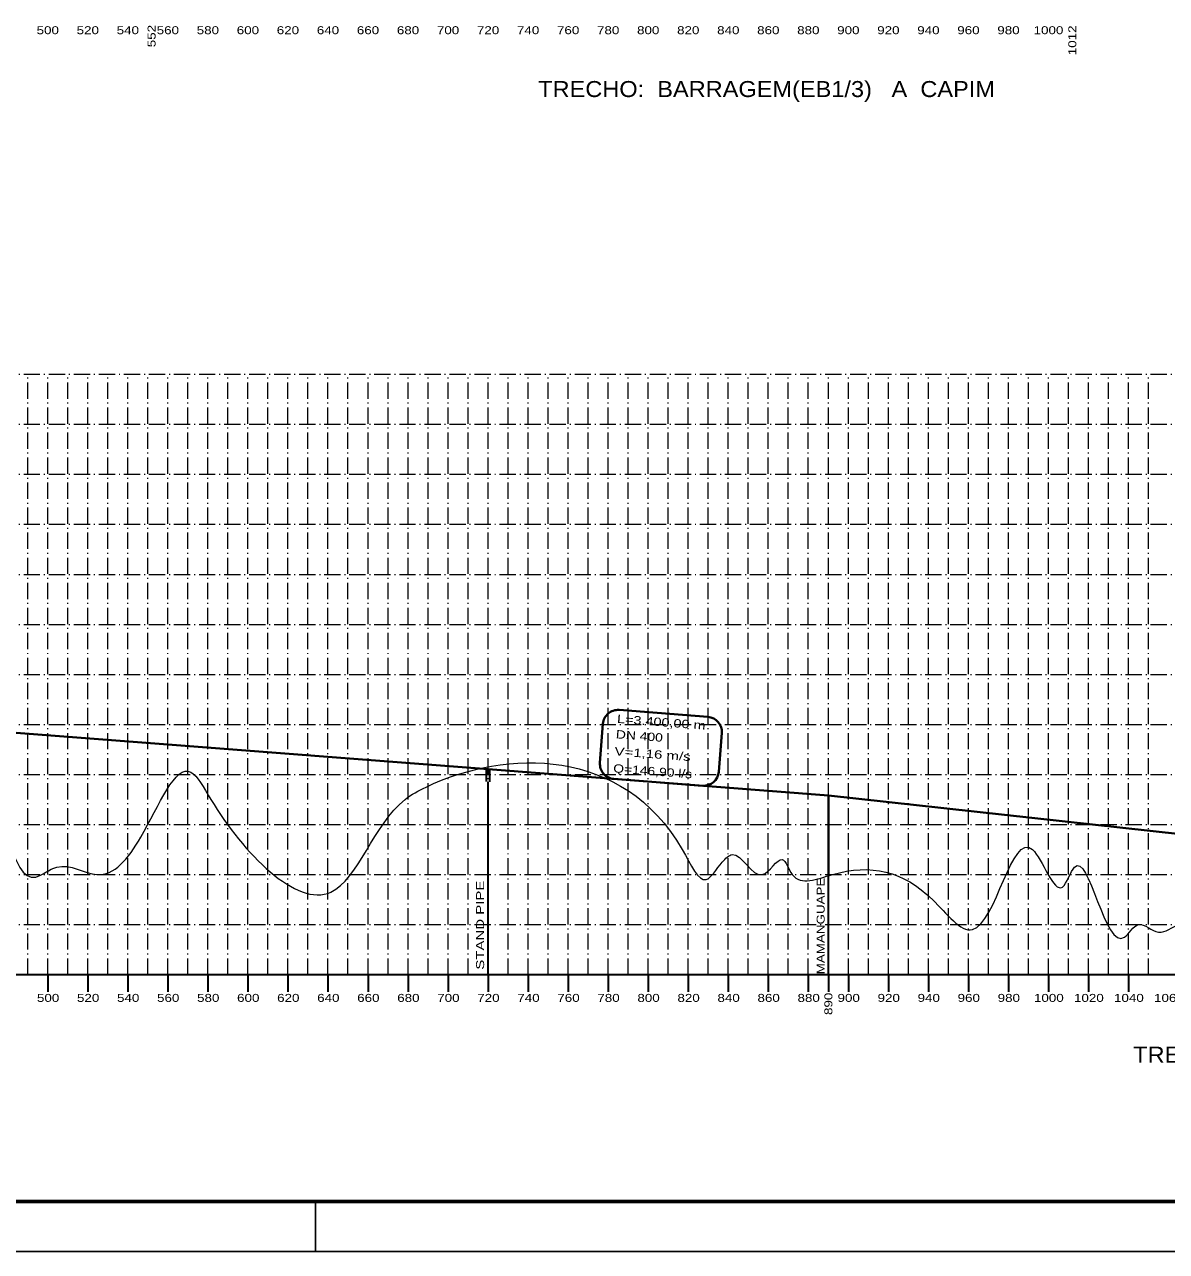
# Model space of a CAD drawing. Extents: x 0 to 1682, y 0 to 1188.
# Drawn here: x 495.5 to 951.9, y -0.1 to 490.3 of the extents above; entities that cross this region are included whole.
import ezdxf
from ezdxf.enums import TextEntityAlignment as Align

# ---------------------------------------------------------------- set-up
doc = ezdxf.new("R2010")
doc.units = 0
doc.header["$LTSCALE"] = 1.3
doc.linetypes.add('DOT_DASHED', pattern=[7.7, 5, -1.2, 0.3, -1.2])
for name, color, linetype, lineweight in [('1', 7, 'DOT_DASHED', 13), ('56', 7, 'Continuous', 13), ('62', 7, 'Continuous', 13), ('63', 7, 'Continuous', 25), ('7', 7, 'Continuous', 35), ('9', 7, 'Continuous', 40)]:
    doc.layers.add(name, color=color, linetype=linetype, lineweight=lineweight)
doc.layers.add('24', color=7, linetype='Continuous')

msp = doc.modelspace()

# ---------------------------------------------------------------- linework, layer by layer
at = {"layer": '1'}
for p, q in [((104.775, 350.521), (1145.575, 350.521)), ((496.775, 110.521), (496.775, 350.521)), ((504.775, 110.521), (504.775, 350.521)), ((512.775, 110.521), (512.775, 350.521)), ((520.775, 110.521), (520.775, 350.521)), ((528.775, 110.521), (528.775, 350.521)), ((536.775, 110.521), (536.775, 350.521)), ((544.775, 110.521), (544.775, 350.521)), ((552.775, 110.521), (552.775, 350.521)), ((560.775, 110.521), (560.775, 350.521)), ((568.775, 110.521), (568.775, 350.521)), ((576.775, 110.521), (576.775, 350.521)), ((584.775, 110.521), (584.775, 350.521)), ((592.775, 110.521), (592.775, 350.521)), ((600.775, 110.521), (600.775, 350.521)), ((608.775, 110.521), (608.775, 350.521)), ((616.775, 110.521), (616.775, 350.521)), ((624.775, 110.521), (624.775, 350.521)), ((632.775, 110.521), (632.775, 350.521)), ((640.775, 110.521), (640.775, 350.521)), ((648.775, 110.521), (648.775, 350.521)), ((656.775, 110.521), (656.775, 350.521)), ((664.775, 110.521), (664.775, 350.521)), ((672.775, 110.521), (672.775, 350.521)), ((680.775, 110.521), (680.775, 350.521)), ((688.775, 110.521), (688.775, 350.521)), ((696.775, 110.521), (696.775, 350.521)), ((704.775, 110.521), (704.775, 350.521)), ((712.775, 110.521), (712.775, 350.521)), ((720.775, 110.521), (720.775, 350.521)), ((728.775, 110.521), (728.775, 350.521)), ((736.775, 110.521), (736.775, 350.521)), ((744.775, 110.521), (744.775, 350.521)), ((752.775, 110.521), (752.775, 350.521)), ((760.775, 110.521), (760.775, 350.521)), ((768.775, 110.521), (768.775, 350.521)), ((776.775, 110.521), (776.775, 350.521)), ((784.775, 110.521), (784.775, 350.521)), ((792.775, 110.521), (792.775, 350.521)), ((800.775, 110.521), (800.775, 350.521)), ((808.775, 110.521), (808.775, 350.521)), ((816.775, 110.521), (816.775, 350.521)), ((824.775, 110.521), (824.775, 350.521)), ((832.775, 110.521), (832.775, 350.521)), ((840.775, 110.521), (840.775, 350.521)), ((848.775, 110.521), (848.775, 350.521)), ((856.775, 110.521), (856.775, 350.521)), ((864.775, 110.521), (864.775, 350.521)), ((872.775, 110.521), (872.775, 350.521)), ((880.775, 110.521), (880.775, 350.521)), ((888.775, 110.521), (888.775, 350.521)), ((896.775, 110.521), (896.775, 350.521)), ((904.775, 110.521), (904.775, 350.521)), ((912.775, 110.521), (912.775, 350.521)), ((920.775, 110.521), (920.775, 350.521)), ((928.775, 110.521), (928.775, 350.521)), ((936.775, 110.521), (936.775, 350.521)), ((944.775, 110.521), (944.775, 350.521)), ((104.775, 330.521), (1145.575, 330.521)), ((104.775, 310.521), (1145.575, 310.521)), ((104.775, 290.521), (1145.575, 290.521)), ((104.775, 270.521), (1145.575, 270.521)), ((104.775, 250.521), (1145.575, 250.521)), ((104.775, 230.521), (1145.575, 230.521)), ((104.775, 210.521), (1145.575, 210.521)), ((104.775, 190.521), (1145.575, 190.521)), ((104.775, 170.521), (1145.575, 170.521)), ((104.775, 150.521), (1145.575, 150.521)), ((104.775, 130.521), (1145.575, 130.521))]:
    msp.add_line(p, q, dxfattribs=at)
at = {"layer": '56'}
msp.add_spline([(104.775, 155.521), (114.375, 150.521), (116.375, 145.521), (117.875, 149.271), (119.975, 160.521), (121.575, 150.521), (123.175, 160.521), (127.975, 170.521), (132.775, 183.521), (136.775, 170.521), (139.175, 155.521), (149.575, 188.521), (177.575, 175.521), (202.375, 180.521), (205.575, 178.521), (209.575, 180.521), (213.575, 183.521), (221.575, 176.521), (229.575, 179.521), (241.575, 175.521), (257.575, 180.521), (273.575, 168.521), (286.375, 190.521), (290.375, 195.521), (303.175, 178.521), (318.375, 190.521), (328.775, 187.521), (340.775, 190.521), (348.775, 180.521), (358.375, 193.521), (366.375, 184.521), (376.775, 200.521), (397.575, 190.521), (415.975, 202.521), (446.375, 175.521), (458.375, 185.521), (463.175, 180.521), (475.975, 181.521), (499.975, 149.521), (508.375, 153.521), (524.375, 150.521), (541.975, 165.521), (561.975, 191.521), (569.975, 180.521), (617.975, 143.521), (647.575, 180.521), (655.975, 185.521), (758.375, 160.521), (767.975, 148.521), (774.375, 155.521), (778.375, 158.521), (790.375, 150.521), (798.375, 156.521), (802.375, 150.521), (818.375, 150.521), (858.375, 140.521), (874.375, 128.521), (898.375, 160.521), (910.375, 145.521), (915.175, 153.521), (935.175, 125.521), (940.775, 130.521), (948.775, 127.521), (956.775, 130.521), (975.975, 120.521), (984.775, 118.521), (995.175, 125.521), (1023.975, 118.521), (1029.575, 120.521), (1033.575, 118.521), (1040.775, 123.521), (1048.775, 118.521), (1068.775, 125.521), (1084.775, 118.521), (1091.175, 123.521), (1095.175, 120.521), (1099.975, 122.521), (1107.975, 117.521), (1114.375, 120.521), (1130.375, 118.521), (1145.575, 118.521)], degree=3, dxfattribs=at)
at = {"layer": '62', "lineweight": 35}
for p, q in [((680.775, 110.521), (680.775, 187.657)), ((816.775, 110.521), (816.775, 150.725)), ((104.775, 110.521), (1145.575, 110.521)), ((504.775, 110.521), (504.775, 103.693)), ((520.775, 110.521), (520.775, 103.693)), ((536.775, 110.521), (536.775, 103.693)), ((552.775, 110.521), (552.775, 103.693)), ((568.775, 110.521), (568.775, 103.693)), ((584.775, 110.521), (584.775, 103.693)), ((600.775, 110.521), (600.775, 103.693)), ((616.775, 110.521), (616.775, 103.693)), ((632.775, 110.521), (632.775, 103.693)), ((648.775, 110.521), (648.775, 103.693)), ((664.775, 110.521), (664.775, 103.693)), ((680.775, 110.521), (680.775, 103.693)), ((696.775, 110.521), (696.775, 103.693)), ((712.775, 110.521), (712.775, 103.693)), ((728.775, 110.521), (728.775, 103.693)), ((744.775, 110.521), (744.775, 103.693)), ((760.775, 110.521), (760.775, 103.693)), ((776.775, 110.521), (776.775, 103.693)), ((792.775, 110.521), (792.775, 103.693)), ((808.775, 110.521), (808.775, 103.693)), ((816.775, 110.521), (816.775, 103.693)), ((824.775, 110.521), (824.775, 103.693)), ((840.775, 110.521), (840.775, 103.693)), ((856.775, 110.521), (856.775, 103.693)), ((872.775, 110.521), (872.775, 103.693)), ((888.775, 110.521), (888.775, 103.693)), ((904.775, 110.521), (904.775, 103.693)), ((920.775, 110.521), (920.775, 103.693)), ((936.775, 110.521), (936.775, 103.693))]:
    msp.add_line(p, q, dxfattribs=at)
at = {"layer": '63', "lineweight": 60}
msp.add_line((1661.832, 19.881), (49.832, 19.881), dxfattribs=at)
at = {"layer": '63'}
msp.add_line((611.832, -0.119), (611.832, 19.881), dxfattribs=at)
for points in [[(-0.168, -0.119), (1681.832, -0.119), (1681.832, 1187.881)], [(-0.168, -0.119), (1681.832, -0.119), (-0.168, -0.119)]]:
    msp.add_lwpolyline(points, dxfattribs=at)
at = {"layer": '63', "lineweight": 60}
msp.add_lwpolyline([(951.544, 19.881), (49.832, 19.881), (49.832, 1167.881)], dxfattribs=at)
at = {"layer": '7'}
msp.add_line((680.081, 187.706), (680.081, 192.439), dxfattribs=at)
msp.add_lwpolyline([(681.468, 187.603), (681.468, 192.439), (680.081, 192.439)], dxfattribs=at)
at = {"layer": '9'}
for p, q in [((733.134, 216.31), (768.663, 213.569)), ((726.69, 210.789), (725.49, 195.225)), ((774.183, 207.126), (772.983, 191.562)), ((731.011, 188.782), (766.539, 186.041)), ((816.775, 150.725), (816.775, 182.165))]:
    msp.add_line(p, q, dxfattribs=at)
msp.add_lwpolyline([(104.775, 243.105), (148.775, 235.835), (256.775, 225.365), (680.775, 192.657), (816.775, 182.165), (1145.575, 145.975)], dxfattribs=at)
for centre, start, end in [((732.673, 210.328), 85.58878, 175.58878), ((768.201, 207.587), 355.58878, 85.58878), ((731.472, 194.764), 175.58877, 265.58877), ((767, 192.023), 265.58877, 355.58877)]:
    msp.add_arc(centre, 6, start, end, dxfattribs=at)

# ---------------------------------------------------------------- texts
at = {"layer": '24'}
for s, height, width, p in [('500', 3.2, 1.25, (504.775, 486.422)), ('520', 3.2, 1.25, (520.775, 486.422)), ('540', 3.2, 1.25, (536.775, 486.422)), ('560', 3.2, 1.25, (552.775, 486.422)), ('580', 3.2, 1.25, (568.775, 486.422)), ('600', 3.2, 1.25, (584.775, 486.422)), ('620', 3.2, 1.25, (600.775, 486.422)), ('640', 3.2, 1.25, (616.775, 486.422)), ('660', 3.2, 1.25, (632.775, 486.422)), ('680', 3.2, 1.25, (648.775, 486.422)), ('700', 3.2, 1.25, (664.775, 486.422)), ('720', 3.2, 1.25, (680.775, 486.422)), ('740', 3.2, 1.25, (696.775, 486.422)), ('760', 3.2, 1.25, (712.775, 486.422)), ('780', 3.2, 1.25, (728.775, 486.422)), ('800', 3.2, 1.25, (744.775, 486.422)), ('820', 3.2, 1.25, (760.775, 486.422)), ('840', 3.2, 1.25, (776.775, 486.422)), ('860', 3.2, 1.25, (792.775, 486.422)), ('880', 3.2, 1.25, (808.775, 486.422)), ('900', 3.2, 1.25, (824.775, 486.422)), ('920', 3.2, 1.25, (840.775, 486.422)), ('940', 3.2, 1.25, (856.775, 486.422)), ('960', 3.2, 1.25, (872.775, 486.422)), ('980', 3.2, 1.25, (888.775, 486.422)), ('1000', 3.2, 1.25, (904.775, 486.422)), ('TRECHO:  BARRAGEM(EB1/3)   A  CAPIM', 6.4, 1.1, (792.086, 461.309)), ('500', 3.2, 1.25, (504.915, 99.629)), ('520', 3.2, 1.25, (520.915, 99.629)), ('540', 3.2, 1.25, (536.915, 99.629)), ('560', 3.2, 1.25, (552.915, 99.629)), ('580', 3.2, 1.25, (568.915, 99.629)), ('600', 3.2, 1.25, (584.915, 99.629)), ('620', 3.2, 1.25, (600.915, 99.629)), ('640', 3.2, 1.25, (616.915, 99.629)), ('660', 3.2, 1.25, (632.915, 99.629)), ('680', 3.2, 1.25, (648.915, 99.629)), ('700', 3.2, 1.25, (664.915, 99.629)), ('720', 3.2, 1.25, (680.915, 99.629)), ('740', 3.2, 1.25, (696.915, 99.629)), ('760', 3.2, 1.25, (712.915, 99.629)), ('780', 3.2, 1.25, (728.915, 99.629)), ('800', 3.2, 1.25, (744.915, 99.629)), ('820', 3.2, 1.25, (760.915, 99.629)), ('840', 3.2, 1.25, (776.915, 99.629)), ('860', 3.2, 1.25, (792.915, 99.629)), ('880', 3.2, 1.25, (808.915, 99.629)), ('900', 3.2, 1.25, (824.915, 99.629)), ('920', 3.2, 1.25, (840.915, 99.629)), ('940', 3.2, 1.25, (856.915, 99.629)), ('960', 3.2, 1.25, (872.915, 99.629)), ('980', 3.2, 1.25, (888.915, 99.629)), ('1000', 3.2, 1.25, (904.915, 99.629)), ('1020', 3.2, 1.25, (920.915, 99.629)), ('1040', 3.2, 1.25, (936.915, 99.629)), ('1060', 3.2, 1.25, (952.915, 99.629)), ('TRECHO:  BARRAGEM(EB1/2)   A  RIO TINTO', 6.4, 1.1, (1038.803, 75.355))]:
    msp.add_text(s, height=height, dxfattribs=dict(at, width=width)).set_placement(p, align=Align.CENTER)
at = {"layer": '24', "width": 1.25}
for s, p in [('552', (547.867, 485.684)), ('1012', (915.893, 483.976)), ('890', (818.391, 98.851))]:
    msp.add_text(s, height=3.2, rotation=90, dxfattribs=at).set_placement(p, align=Align.CENTER)
at = {"layer": '24'}
for s, width, p in [('STAND PIPE', 1.4, (679.184, 112.507)), ('MAMANGUAPE', 1.25, (815.305, 110.669))]:
    msp.add_text(s, height=3.2, rotation=90, dxfattribs=dict(at, width=width)).set_placement(p)
at = {"layer": '9'}
for s, width, p in [('L=3.400,00 m', 1.3, (732.222, 211.187)), ('DN 400', 1.25, (731.747, 205.025)), ('V=1,16 m/s', 1.35, (731.222, 198.222)), ('Q=146,90 l/s', 1.25, (730.697, 191.418))]:
    msp.add_text(s, height=3.319, rotation=355.589, dxfattribs=dict(at, width=width)).set_placement(p)

doc.saveas('drawing.dxf')
